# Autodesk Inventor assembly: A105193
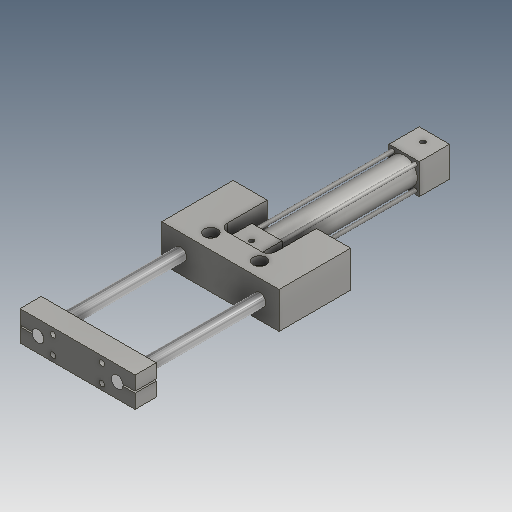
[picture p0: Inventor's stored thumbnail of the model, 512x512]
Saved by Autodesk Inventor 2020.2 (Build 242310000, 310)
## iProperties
Created: 1999-12
Part Number: A105193
Description: PHD SLIDE SDC22X4.0
Document SubType Name: Assembly
Designer: glanglot
Mass: 855.699 g
Surface Area: 683.341 cm^2
Volume: 261.079 cm^3
Density: 3.27755 g/cm^3
Control State: 0
Master: False
Checked Out: False
Shininess: 0.0
Length Units: 11269
Angle Units: 11279
Time Units: 11290
Mass Units: 11286
Length Display Precision: 3
Angle Display Precision: 2
Compacted: True
Dimensions: 30,5x299,4x98,5 mm
Mass: 1,886 lb
Density: 0.0
Volumn: 0.0
Area: 0.0
PropertySet Name: Model Information
Author: glanglot
Revision Number: -
Title: PHD SLIDE SDC22X4.0
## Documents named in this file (5)
- D:\07 - DEMODATEN\OTX 2019 - Dataset - UPDATE - Dez2019\Designs\07-Packing machine\A105193.iam
- D:\07 - DEMODATEN\OTX 2019 - Dataset - UPDATE - Dez2019\Designs\07-Packing machine\Parts\ADSK-011806.ipt
- D:\07 - DEMODATEN\OTX 2019 - Dataset - UPDATE - Dez2019\Designs\07-Packing machine\Parts\ADSK-011808.ipt
- D:\07 - DEMODATEN\OTX 2019 - Dataset - UPDATE - Dez2019\Designs\07-Packing machine\Parts\ADSK-011807.ipt
- D:\07 - DEMODATEN\OTX 2019 - Dataset - UPDATE - Dez2019\Designs\07-Packing machine\Parts\ADSK-011809.ipt
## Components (5 placed, 4 different names)
1. ADSK-011806:1 — STROKE, Mate:2, Mate:3, Flush:1, Mate:4, Mate:5, Flush:2, Flush:3, Flush:4
2. ADSK-011807:1 — STROKE, Insert:1, Insert:2
3. ADSK-011808:1 — Insert:2, Mate:2
4. ADSK-011808:2 — Insert:1, Mate:3
5. ADSK-011809:1 — Flush:1, Mate:4, Mate:5
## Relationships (11: Mate 5, Flush 4, Insert 2)
- STROKE [Mate]: ADSK-011806:1 ↔ ADSK-011807:1
- Insert:1: ADSK-011807:1 ↔ ADSK-011808:2
- Insert:2: ADSK-011807:1 ↔ ADSK-011808:1
- Mate:2: ADSK-011806:1 ↔ ADSK-011808:1
- Mate:3: ADSK-011806:1 ↔ ADSK-011808:2
- Flush:1: ADSK-011806:1 ↔ ADSK-011809:1
- Mate:4: ADSK-011806:1 ↔ ADSK-011809:1
- Mate:5: ADSK-011806:1 ↔ ADSK-011809:1
- Flush:2: ADSK-011806:1
- Flush:3: ADSK-011806:1
- Flush:4: ADSK-011806:1
